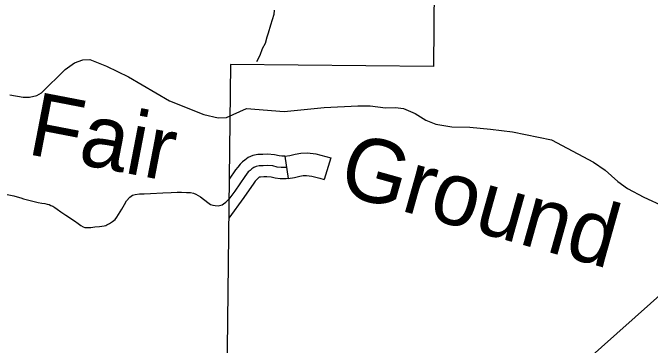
# Model space of a CAD drawing. Extents: x 1377389 to 1380723, y 1168351 to 1170484.
# Drawn here: x 1378786.6 to 1378871.6, y 1168953.2 to 1168997.5 of the extents above; entities that cross this region are included whole.
import ezdxf

# ---------------------------------------------------------------- set-up
doc = ezdxf.new("R2010")
doc.units = 0
doc.layers.add('B_Contour_Elevations', color=7, linetype='Continuous')
doc.layers.add('B_Fill', color=7, linetype='Continuous')

msp = doc.modelspace()

# ---------------------------------------------------------------- linework, layer by layer
at = {"layer": 'B_Contour_Elevations'}
msp.add_line((1378478.497, 1168608.298), (1379068.402, 1169134.14), dxfattribs=at)
at = {"layer": 'B_Fill'}
msp.add_line((1378822.87, 1168978.34), (1378823.343, 1168975.377), dxfattribs=at)
for points in [[(1378842.915, 1169016.795), (1378842.687, 1168990.301)], [(1378821.472, 1168997.813), (1378821.394, 1168997.228), (1378821.199, 1168996.527), (1378820.966, 1168995.826), (1378820.654, 1168994.735), (1378820.46, 1168994.228), (1378820.265, 1168993.371), (1378819.876, 1168992.67), (1378819.525, 1168991.774), (1378819.097, 1168990.955)], [(1378786.216, 1168986.52), (1378787.98, 1168986.214), (1378788.818, 1168986.22), (1378789.808, 1168986.45), (1378790.455, 1168986.81), (1378793.589, 1168989.929), (1378794.858, 1168990.809), (1378795.943, 1168991.182), (1378796.899, 1168991.252), (1378799.082, 1168990.338), (1378802.018, 1168988.928), (1378807.524, 1168985.715), (1378812.068, 1168983.934), (1378813.978, 1168983.452), (1378815.093, 1168983.527), (1378817.769, 1168984.71), (1378822.788, 1168984.304), (1378828.138, 1168984.829), (1378832.598, 1168985.087), (1378834.234, 1168985.057), (1378836.297, 1168984.8), (1378837.612, 1168984.841), (1378838.693, 1168984.734), (1378840.27, 1168984.062), (1378841.675, 1168983.145), (1378843.027, 1168982.646), (1378845.132, 1168982.291), (1378847.529, 1168982.204), (1378850.289, 1168981.969), (1378853.232, 1168981.6), (1378858.433, 1168980.519), (1378864.031, 1168977.549), (1378865.579, 1168976.516), (1378867.283, 1168974.968), (1378868.548, 1168974.066), (1378870.739, 1168972.893), (1378873.451, 1168971.656)], [(1378842.687, 1168990.301), (1378815.63, 1168990.588), (1378815.024, 1168937.482)], [(1378842.687, 1168990.301), (1378815.63, 1168990.588), (1378815.024, 1168937.482)], [(1378822.87, 1168978.34), (1378822.87, 1168978.34), (1378822.483, 1168978.348), (1378822.14, 1168978.392), (1378821.495, 1168978.543), (1378820.549, 1168978.607), (1378819.953, 1168978.592), (1378819.265, 1168978.561), (1378818.61, 1168978.434), (1378818.005, 1168978.182), (1378817.533, 1168977.844), (1378817.243, 1168977.587), (1378816.927, 1168977.305), (1378816.591, 1168976.898), (1378816.306, 1168976.523), (1378815.455, 1168975.274)], [(1378822.87, 1168978.34), (1378823.555, 1168978.449), (1378824.245, 1168978.622), (1378825, 1168978.77), (1378825.885, 1168978.787), (1378826.992, 1168978.677), (1378828.356, 1168978.332), (1378829.01, 1168978.128), (1378828.114, 1168975.265)], [(1378823.106, 1168976.858), (1378822.973, 1168976.837), (1378822.372, 1168976.85), (1378821.873, 1168976.914), (1378821.272, 1168977.055), (1378820.517, 1168977.106), (1378820.005, 1168977.093), (1378819.443, 1168977.068), (1378819.046, 1168976.991), (1378818.739, 1168976.863), (1378818.471, 1168976.671), (1378818.24, 1168976.466), (1378818.01, 1168976.261), (1378817.767, 1168975.967), (1378817.524, 1168975.647), (1378816.207, 1168973.714), (1378815.414, 1168972.638)], [(1378823.343, 1168975.377), (1378824.156, 1168975.507), (1378824.898, 1168975.693), (1378825.32, 1168975.775), (1378825.766, 1168975.784), (1378826.474, 1168975.714), (1378827.54, 1168975.444), (1378828.114, 1168975.265)], [(1378823.343, 1168975.377), (1378823.076, 1168975.335), (1378822.26, 1168975.352), (1378821.606, 1168975.436), (1378821.048, 1168975.566), (1378820.485, 1168975.605), (1378820.058, 1168975.594), (1378819.62, 1168975.574), (1378819.482, 1168975.547), (1378819.473, 1168975.544), (1378819.408, 1168975.497), (1378819.237, 1168975.345), (1378819.094, 1168975.217), (1378818.943, 1168975.035), (1378818.742, 1168974.77), (1378817.431, 1168972.846), (1378815.396, 1168970.087)], [(1378785.881, 1168973.265), (1378786.737, 1168973.061), (1378787.197, 1168972.945), (1378787.683, 1168972.792), (1378788.041, 1168972.677), (1378788.553, 1168972.536), (1378789.269, 1168972.344), (1378789.998, 1168972.19), (1378790.484, 1168972.113), (1378790.894, 1168972.037), (1378791.188, 1168971.973), (1378791.456, 1168971.896), (1378791.699, 1168971.793), (1378791.93, 1168971.678), (1378792.237, 1168971.499), (1378792.505, 1168971.307), (1378793.017, 1168970.961), (1378793.682, 1168970.513), (1378794.846, 1168969.72), (1378795.332, 1168969.374), (1378795.69, 1168969.131), (1378795.971, 1168968.951), (1378796.227, 1168968.862), (1378796.457, 1168968.862), (1378797.02, 1168968.862), (1378797.544, 1168968.939), (1378798.184, 1168969.003), (1378798.785, 1168969.054), (1378799.003, 1168969.118), (1378799.169, 1168969.195), (1378799.335, 1168969.284), (1378799.489, 1168969.374), (1378799.907, 1168969.63), (1378800.239, 1168969.912), (1378800.495, 1168970.219), (1378801.16, 1168971.294), (1378801.489, 1168971.921), (1378801.783, 1168972.408), (1378802.205, 1168972.907), (1378802.589, 1168973.15), (1378802.947, 1168973.253), (1378803.484, 1168973.342), (1378804.137, 1168973.342), (1378804.981, 1168973.394), (1378806.631, 1168973.458), (1378807.727, 1168973.522), (1378808.533, 1168973.56), (1378809.083, 1168973.56), (1378809.773, 1168973.534), (1378810.298, 1168973.509), (1378810.707, 1168973.445), (1378811.001, 1168973.304), (1378811.641, 1168972.933), (1378812.613, 1168972.165), (1378812.971, 1168971.934), (1378813.278, 1168971.832), (1378813.61, 1168971.793), (1378814.007, 1168971.755), (1378814.327, 1168971.819), (1378814.518, 1168971.883), (1378814.71, 1168971.998), (1378815.004, 1168972.216), (1378815.414, 1168972.638)]]:
    msp.add_lwpolyline(points, dxfattribs=at)

# ---------------------------------------------------------------- texts
for s, rotation, p in [('Fair', 349.08651, (1378788.374, 1168978.666)), ('Ground', 344.32656, (1378829.699, 1168973.52))]:
    msp.add_text(s, height=8.448, rotation=rotation, dxfattribs=at).set_placement(p)

doc.saveas('drawing.dxf')
